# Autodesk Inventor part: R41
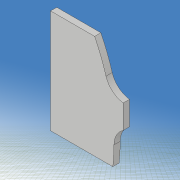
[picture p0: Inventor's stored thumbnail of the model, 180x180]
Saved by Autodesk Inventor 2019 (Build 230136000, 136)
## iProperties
Created: 2021-05
Part Number: R41
Material: 一般
Document SubType Name: Modeling
Designer: kikut
Density: 1 g/cm^3
Appearance: 既定
Mass: 0.0213701 g
Surface Area: 0.855673 cm^2
Volume: 0.0213701 cm^3
Author: kikut
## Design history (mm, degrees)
sketch "スケッチ1"
  geometry: L1 (80, 60)-(-80, 60); L2 (-80, 60)-(-80, -60); L3 (-80, -60)-(80, -60); L4 (80, -60)-(80, 60); L5 (80, 60)-(-80, -60); L6 (-80, 60)-(80, -60); 1 further point
  constraints: 12 end point, 2 midpoint, 2 parallel, 1 horizontal, 1 perpendicular
  dimensions: "d0" = 160 distance of L2.end L3.end; "d1" = 120 distance of L1.end L2.end
extrude "押し出し1" new body sketch "スケッチ1" stored distance "d2" = 0.6; taper "d3" = 0 deg
sketch "スケッチ2"
  geometry: L1 (-140, 0)-(140, 0) reference; L2 (0, -54)-(20, -30); L3 (0, 54)-(20, 30); L4 (0, -3)-(6.514, -3); L5 (6.514, -3)-(16, -6); L6 (16, -6)-(24, -3); L7 (24, -3)-(33.716, -3); L8 (0, 3)-(6.514, 3); L9 (6.514, 3)-(16, 6); L10 (16, 6)-(24, 3); L11 (24, 3)-(33.716, 3); L12 (0, -98)-(0, 98) reference; L13 (-100, -70)-(100, -70); L14 (100, -70)-(100, 70); L15 (100, 70)-(-100, 70); L16 (-100, 70)-(-100, -70); L17 (-100, -70)-(100, 70); L18 (100, -70)-(-100, 70); A1 r 60 centre (54.312, 28.5) between (0, 54) and (0, 3); A2 r 60 centre (54.312, -28.5) between (0, -3) and (0, -54); A3 r 18.111 centre (18, -12) between (20, -30) and (33.716, -3); A4 r 18.111 centre (18, 12) between (33.716, 3) and (20, 30); 1 further point
  constraints: 32 end point, 8 point on circle, 8 symmetric about line, 4 centre point, 3 horizontal, 2 collinear, 2 midpoint, 2 parallel, 1 perpendicular
  dimensions: "d5" = 60 radius of A1; "d6" = 6 distance of L8.start L4.start; "d7" = 108 distance of L3.start L2.start; "d8" = 0 horizontal distance of L3.start L8.start; "d9" = 60 distance of L3.end L2.end; "d10" = 0 horizontal distance of point (0, 0) L3.start; "d11" = 20 horizontal distance of L3.start L3.end; "d12" = 24 distance of A4.centre A3.centre; "d13" = 6 distance of L11.end L7.end; "d14" = 12 distance of L9.end L5.end; "d15" = 16 distance from line of L12 L5.end; "d16" = 24 distance from line of L6.end L12; "d17" = 200 distance of L14.end L15.end; "d18" = 140 distance of L15.end L13.start; "d30" = 18 distance from line of L12 A4.centre
extrude "押し出し2" cut sketch "スケッチ2" stored distance "d19" = 10; taper "d20" = 0 deg
sketch "スケッチ3"
  geometry: L1 (49.705, -17.97)-(33.948, -15.191); L2 (33.948, -15.191)-(34.295, -13.222); L3 (34.295, -13.222)-(50.052, -16); L4 (50.052, -16)-(49.705, -17.97); L5 (49.705, -17.97)-(34.295, -13.222); L6 (33.948, -15.191)-(50.052, -16); L7 (50.052, 16)-(34.295, 13.222); L8 (34.295, 13.222)-(33.948, 15.191); L9 (33.948, 15.191)-(49.705, 17.97); L10 (49.705, 17.97)-(50.052, 16); L11 (50.052, 16)-(33.948, 15.191); L12 (34.295, 13.222)-(49.705, 17.97); L13 (-112, 0)-(112, 0) reference; L14 (0, -84)-(0, 84) reference; 3 further points
  constraints: 24 end point, 4 midpoint, 4 parallel, 2 perpendicular, 2 symmetric about line
  dimensions: "d21" = 2 distance of L3.end L1.start; "d22" = 2 distance of L9.end L7.start; "d23" = 16 distance of L8.end L9.end; "d24" = 42 distance from line of L14 point (42, 15.596); "d26" = 10 deg angle of L7 L13; "d62" = 16 distance from line of L3.end L13
extrude "押し出し3" join sketch "スケッチ3" distance "d27" = 0.6; taper "d28" = 0 deg
fillet "フィレット1" dims "d31" = 2
fillet "フィレット2" dims "d32" = 1
sketch "スケッチ6"
  geometry: L1 (-20, 60)-(80, 60); L2 (80, 60)-(80, -60); L3 (80, -60)-(-20, -60); L4 (-20, -60)-(-20, 60); L5 (-46.168, 0)-(93.832, 0) reference; L6 (0, -84)-(0, 84) reference; L7 (30, 10)-(37, 10); L8 (37, 10)-(37, 20); L9 (37, 20)-(30, 20); L10 (30, 20)-(30, 10); 1 further point
  constraints: 16 end point, 4 parallel, 2 horizontal, 2 perpendicular, 1 other
  dimensions: "d63" = 120 distance of L3.end L1.start; "d64" = 100 distance of L1.start L1.end; "d65" = 20 distance between parallel lines of L6 L4; "d66" = 7 distance of L8.end L9.end; "d73" = 10 distance of L9.end L7.start; "d74" = 10 distance between parallel lines of L7 L5; "d75" = 50 distance between parallel lines of L10 L4
extrude "押し出し4" cut sketch "スケッチ6" stored distance "d70" = 10; taper "d71" = 0 deg
node "ソリッド1"
